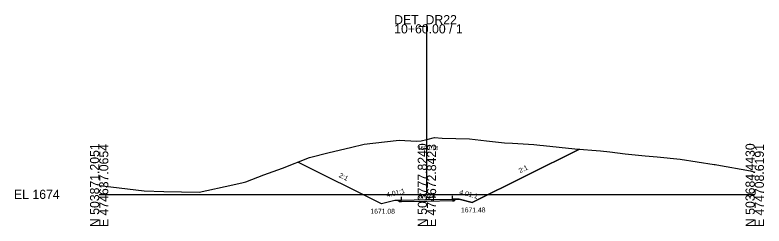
# Model space of a CAD drawing. Extents: x -26 to 1203, y -10 to 9633.
# Drawn here: x -25.7 to 202.8, y 1490.3 to 1554.9 of the extents above; entities that cross this region are included whole.
import ezdxf

# ---------------------------------------------------------------- set-up
doc = ezdxf.new("R2010")
doc.units = 0
for name, color, linetype in [('Exist Cross Section Cell', 7, 'Continuous'), ('Exist XS Center Line Elevation Label', 7, 'Continuous'), ('Exist XS Ground Line', 7, 'Continuous'), ('Prop XS Ditch Slope Text', 7, 'Continuous'), ('Prop XS Ditch Standard Text', 7, 'Continuous'), ('Prop XS Earthwork Shape', 7, 'Continuous'), ('Prop XS EOT Tick Mark', 7, 'Continuous'), ('Prop XS Finish Grade', 7, 'Continuous'), ('Prop XS Finish Grade Earthwork', 7, 'Continuous'), ('Prop XS Finish Grade Pavement', 7, 'Continuous'), ('Prop XS Pvmt Edge Slope', 7, 'Continuous'), ('Prop XS SE Text', 7, 'Continuous'), ('Prop XS Shoulder Borrow Shape', 7, 'Continuous'), ('Prop XS Side Slope Text', 7, 'Continuous'), ('Prop XS Subgrade Earthwork', 7, 'Continuous')]:
    doc.layers.add(name, color=color, linetype=linetype)

msp = doc.modelspace()

# ---------------------------------------------------------------- linework, layer by layer
at = {"layer": 'Exist Cross Section Cell'}
for p, q in [((100, 1500), (100, 1552.02)), ((0, 1500), (100, 1500)), ((100, 1500), (200, 1500))]:
    msp.add_line(p, q, dxfattribs=at)
at = {"layer": 'Exist XS Ground Line'}
msp.add_lwpolyline([(0, 1502.69), (1.03, 1502.57), (13.77, 1501.04), (19.69, 1500.85), (30.46, 1500.64), (40.79, 1502.94), (43.91, 1503.62), (44.74, 1503.83), (50.26, 1505.93), (55.91, 1508.05), (64.2, 1511.28), (70.14, 1512.83), (76.65, 1514.33), (80.85, 1515.3), (83.45, 1515.64), (91.56, 1516.55), (96.82, 1516.29), (98.27, 1516.35), (100, 1516.78), (102.27, 1517.34), (104.6, 1517.23), (112.98, 1516.94), (118.18, 1516.37), (123.69, 1515.79), (126.15, 1515.66), (132.56, 1515.2), (134.4, 1515.08), (135.54, 1514.93), (145.11, 1513.89), (152.91, 1513.32), (155.82, 1512.99), (160.52, 1512.42), (166.53, 1511.74), (170.27, 1511.43), (177.24, 1510.8), (187.63, 1509.14), (187.96, 1509.09), (188.47, 1509.01), (198.67, 1507.2), (200, 1506.82)], dxfattribs=at)
at = {"layer": 'Prop XS Earthwork Shape'}
msp.add_lwpolyline([(135.54, 1514.93), (145.11, 1513.89), (146.5, 1513.79), (113.82, 1497.48), (109.81, 1498.48), (108.83, 1498.51), (108.34, 1498.02), (107.81, 1498.01), (100, 1497.86), (92.19, 1497.7), (91.64, 1497.69), (91.16, 1498.16), (90.19, 1498.08), (86.18, 1497.08), (60.57, 1509.87), (64.2, 1511.28), (70.14, 1512.83), (76.65, 1514.33), (80.85, 1515.3), (83.45, 1515.64), (91.56, 1516.55), (96.82, 1516.29), (98.27, 1516.35), (100, 1516.78), (102.27, 1517.34), (104.6, 1517.23), (112.98, 1516.94), (118.18, 1516.37), (123.69, 1515.79), (126.15, 1515.66), (132.56, 1515.2), (134.4, 1515.08)], close=True, dxfattribs=at)
at = {"layer": 'Prop XS EOT Tick Mark'}
for p, q in [((92.19, 1498.24), (92.19, 1499.24)), ((107.81, 1498.56), (107.81, 1499.56))]:
    msp.add_line(p, q, dxfattribs=at)
at = {"layer": 'Prop XS Finish Grade'}
for p, q in [((92.19, 1498.24), (91.16, 1498.16)), ((107.81, 1498.56), (108.83, 1498.51))]:
    msp.add_line(p, q, dxfattribs=at)
at = {"layer": 'Prop XS Finish Grade Earthwork'}
for p, q in [((113.82, 1497.48), (146.5, 1513.79)), ((86.18, 1497.08), (60.57, 1509.87)), ((90.19, 1498.08), (86.18, 1497.08)), ((91.16, 1498.16), (90.19, 1498.08)), ((108.83, 1498.51), (109.81, 1498.48)), ((109.81, 1498.48), (113.82, 1497.48))]:
    msp.add_line(p, q, dxfattribs=at)
at = {"layer": 'Prop XS Finish Grade Pavement'}
for p, q in [((92.19, 1498.24), (100, 1498.4)), ((100, 1498.4), (107.81, 1498.56))]:
    msp.add_line(p, q, dxfattribs=at)
at = {"layer": 'Prop XS Pvmt Edge Slope'}
for p, q in [((92.19, 1498.24), (91.64, 1497.69)), ((107.81, 1498.56), (108.34, 1498.02))]:
    msp.add_line(p, q, dxfattribs=at)
at = {"layer": 'Prop XS Shoulder Borrow Shape'}
for points in [[(92.19, 1498.24), (91.64, 1497.69), (91.16, 1498.16)], [(108.34, 1498.02), (108.83, 1498.51), (107.81, 1498.56)]]:
    msp.add_lwpolyline(points, close=True, dxfattribs=at)
at = {"layer": 'Prop XS Subgrade Earthwork'}
for p, q in [((91.64, 1497.69), (91.16, 1498.16)), ((92.19, 1497.7), (91.64, 1497.69)), ((100, 1497.86), (92.19, 1497.7)), ((107.81, 1498.01), (100, 1497.86)), ((107.81, 1498.01), (108.34, 1498.02)), ((108.34, 1498.02), (108.83, 1498.51))]:
    msp.add_line(p, q, dxfattribs=at)

# ---------------------------------------------------------------- texts
at = {"layer": 'Exist Cross Section Cell'}
for s, p in [('DET_DR22', (90, 1552.02)), ('10+60.00 / 1', (90, 1549.22)), ('EL 1674', (-26, 1498.6))]:
    msp.add_text(s, height=2.8, dxfattribs=at).set_placement(p)
for s, p in [('N 503871.2051', (0, 1490)), ('E 474637.0654', (2.8, 1490)), ('N 503777.8240', (100, 1490)), ('E 474672.8423', (102.8, 1490)), ('N 503684.4430', (200, 1490)), ('E 474708.6191', (202.8, 1490))]:
    msp.add_text(s, height=2.8, rotation=90, dxfattribs=at).set_placement(p)
at = {"layer": 'Exist XS Center Line Elevation Label'}
msp.add_text('1690.78', height=1.25, dxfattribs=at).set_placement((97.15, 1513.53))
at = {"layer": 'Prop XS Ditch Slope Text'}
for rotation, p in [(14.012, (87.82, 1499.04)), (345.988, (109.76, 1500.03))]:
    msp.add_text('4.01:1', height=1.5, rotation=rotation, dxfattribs=at).set_placement(p)
at = {"layer": 'Prop XS Ditch Standard Text'}
for s, p in [('1671.08', (82.74, 1494.08)), ('1671.48', (110.38, 1494.48))]:
    msp.add_text(s, height=1.5, dxfattribs=at).set_placement(p)
at = {"layer": 'Prop XS SE Text'}
msp.add_text('0.020', height=1.5, rotation=1.1458, dxfattribs=at).set_placement((97.4, 1498.77))
at = {"layer": 'Prop XS Side Slope Text'}
for rotation, p in [(26.5237, (128.43, 1506.44)), (333.4763, (72.98, 1505.35))]:
    msp.add_text('2:1', height=1.5, rotation=rotation, dxfattribs=at).set_placement(p)

doc.saveas('drawing.dxf')
